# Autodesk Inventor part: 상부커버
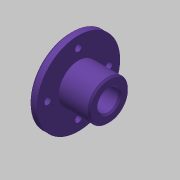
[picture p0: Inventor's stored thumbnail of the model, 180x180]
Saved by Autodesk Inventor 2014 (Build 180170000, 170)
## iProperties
Created: 2015-09
Part Number: 상부커버
Material: 알루미늄 6061
Document SubType Name: Modeling
Designer: mduedu
Density: 1 g/cm^3
Appearance: Violet
Author: mduedu
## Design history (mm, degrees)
sketch "스케치1"
  geometry: L1 (-12.5, 0)-(12.5, 0); L2 (-12.5, 0)-(-12.5, 27); L3 (-12.5, 27)-(-7.5, 27); L4 (-7.5, 27)-(-7.5, 13); L5 (-7.5, 13)-(12.5, 13); L6 (12.5, 13)-(12.5, 0); 2 further points
  constraints: 12 end point, 2 parallel, 2 perpendicular, 1 coincident, 1 horizontal, 1 midpoint, 1 vertical
  dimensions: "d0" = 25 distance of L1.start L1.end; "d2" = 5 distance of L2.end L3.end; "d3" = 26 diameter of L5 L1; "d4" = 54 diameter of L3 L1
revolve "회전1" sketch "스케치1" stored, may be unused: angle "d5" = 90 deg
hole "구멍1" diameter "d8" = 14; stored, may be unused: countersink angle "d12" = 90 deg, drill point angle "d14" = 118 deg; dims "d6" = 10, "d7" = 10, "d9" = 6, "d10" = 4, "d11" = 2, "d13" = 8
chamfer "모따기1" distance "d15" = 1; stored, may be unused: second distance "d16" = 2, angle "d17" = 45 deg
chamfer "모따기2" distance "d18" = 1; stored, may be unused: second distance "d19" = 2, angle "d20" = 45 deg
sketch "스케치2" dims "d21" = 40
  geometry: 6 further points
  constraints: 2 vertical alignment, 1 coincident, 7 other
  dimensions: "d25" = 360 deg dimension on point (0, 0) point (0, 20) (derived)
sketch "스케치3"
  geometry: 4 further points
hole "구멍2" sketch "스케치3" at (0, 20), (-20, 0), (20, 0), (0, -20) diameter "d27" = 4.5; stored, may be unused: countersink angle "d31" = 90 deg, drill point angle "d33" = 0 deg; dims "d28" = 6, "d29" = 4, "d30" = 2, "d32" = 8
chamfer "모따기3" distance "d34" = 1; stored, may be unused: second distance "d35" = 2, angle "d36" = 45 deg
node "솔리드1"
